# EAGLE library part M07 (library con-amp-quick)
AMP QUICK CONNECTOR
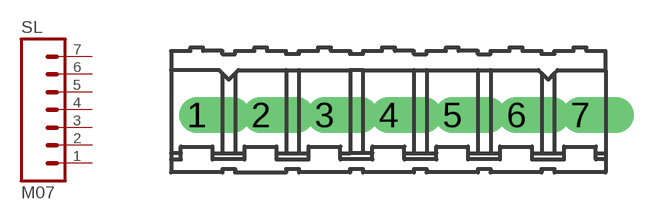
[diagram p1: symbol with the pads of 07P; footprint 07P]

Designator prefix SL

## M07  [07P]
1  1  pas
2  2  pas
3  3  pas
4  4  pas
5  5  pas
6  6  pas
7  7  pas

## Footprint 07P (pad centres in mm)
AMP QUICK CONNECTOR
drill 0.914 offset: 1 -7.62,0; 2 -5.08,0; 3 -2.54,0; 4 0,0; 5 2.54,0; 6 5.08,0; 7 7.62,0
